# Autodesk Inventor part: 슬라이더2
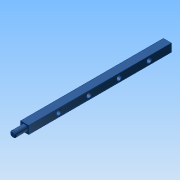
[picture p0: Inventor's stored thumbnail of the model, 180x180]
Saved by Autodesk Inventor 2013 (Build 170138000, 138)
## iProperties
Company: 한국ATC센터
Created: 2015-04
Part Number: 슬라이더2
Document SubType Name: Modeling
Designer: KYOUNG IL JANG
Density: 7.85 g/cm^3
Material: 강
Mass: 69.0062 g
Surface Area: 52.3143 cm^2
Volume: 8.7906 cm^3
Author: KYOUNG IL JANG
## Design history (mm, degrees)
sketch "스케치3"
  geometry: L1 (4, 142)-(-4, 142); L2 (-4, 142)-(-4, 0); L3 (-4, 0)-(4, 0); L4 (4, 0)-(4, 142); 3 further points
  constraints: 8 end point, 2 coincident, 2 parallel, 1 horizontal, 1 midpoint, 1 perpendicular
  dimensions: "d5" = 8 distance of L1.start L1.end; "d6" = 142 distance of L1.end L2.end
extrude "돌출3" new body sketch "스케치3" stored distance "d7" = 8; taper "d8" = 0 deg
sketch "스케치4"
  geometry: L1 (8, 0)-(0, 0) reference; 3 further points
  constraints: 1 midpoint, 1 vertical alignment
  dimensions: "d9" = 30 distance of point (4, 30) point (4, 0)
hole "구멍1" sketch "스케치4" at (4, 30) diameter "d10" = 5; stored, may be unused: countersink angle "d14" = 90 deg, drill point angle "d16" = 118 deg; dims "d11" = 6, "d12" = 4, "d13" = 2, "d15" = 8
sketch "스케치5"
  geometry: C1 r 3 at (4, -4); 1 further point
  constraints: 1 centre point, 1 coincident
  dimensions: "d20" = 6 diameter of C1
extrude "돌출4" join sketch "스케치5" distance "d21" = 12; taper "d22" = 0 deg
chamfer "모따기1" distance "d23" = 1; stored, may be unused: second distance "d24" = 2, angle "d25" = 45 deg
node "작업 평면2"
  node "작업축1"
node "솔리드1"
pattern_linear "직사각형 패턴1" dims "d19" = 30
node "솔리드2"
other parameters: "d26" = 0
